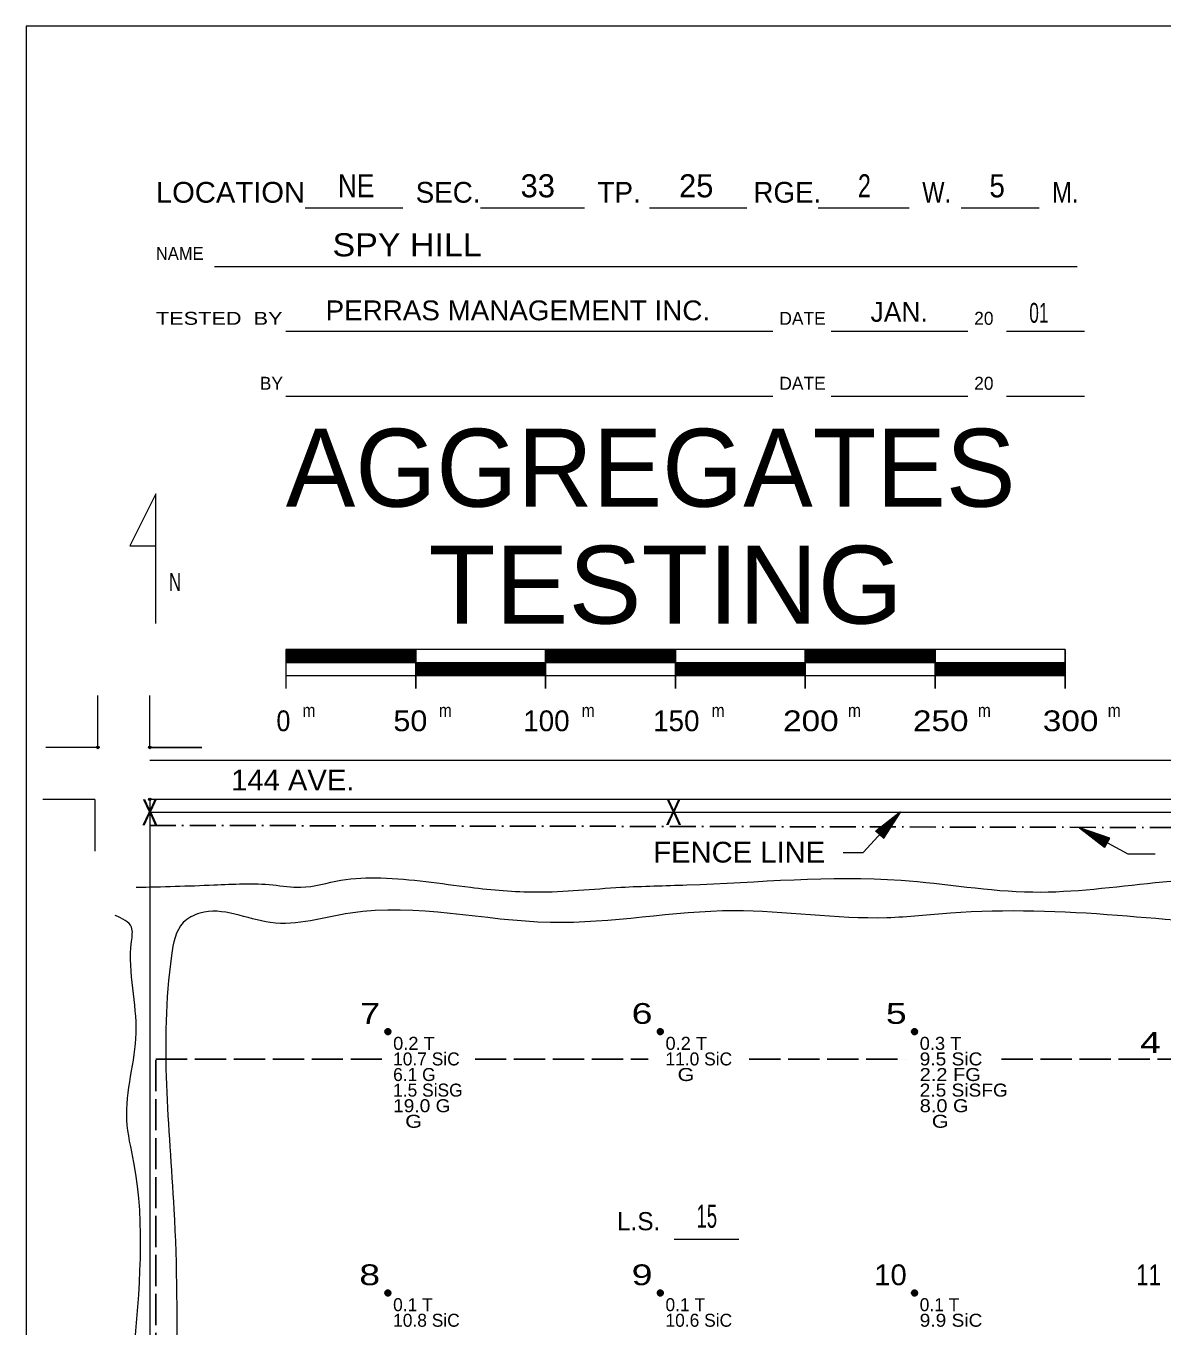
# Model space of a CAD drawing. Extents: x -496 to 480, y -450 to 700.
# Drawn here: x -450 to -12, y 199 to 700 of the extents above; entities that cross this region are included whole.
import ezdxf
from ezdxf.enums import TextEntityAlignment as Align

# ---------------------------------------------------------------- set-up
doc = ezdxf.new("R2010")
doc.units = 0
doc.header["$LTSCALE"] = 2
doc.header["$PDMODE"] = 32
doc.header["$PDSIZE"] = 1
doc.linetypes.add('DOT_DASHED', pattern=[7.7, 5, -1.2, 0.3, -1.2])
doc.linetypes.add('LONG_DASHED', pattern=[7.5, 6, -1.5])
for name, color, linetype, lineweight in [('1', 7, 'Continuous', 13), ('2', 7, 'Continuous', 35), ('3', 7, 'Continuous', 13), ('4', 7, 'Continuous', 25)]:
    doc.layers.add(name, color=color, linetype=linetype, lineweight=lineweight)

msp = doc.modelspace()

# ---------------------------------------------------------------- linework, layer by layer
at = {"layer": '1'}
for p, q in [((-342.517, 629.973), (-305.017, 629.973)), ((-275.017, 629.973), (-235.017, 629.973)), ((-210.017, 629.973), (-172.517, 629.973)), ((-145.017, 629.973), (-110.017, 629.973)), ((-90.017, 629.973), (-60.017, 629.973)), ((-377.517, 607.473), (-45.359, 607.473)), ((-350.017, 582.473), (-162.517, 582.473)), ((-140.017, 582.473), (-87.517, 582.473)), ((-72.517, 582.473), (-42.517, 582.473)), ((-350.017, 557.473), (-162.517, 557.473)), ((-140.017, 557.473), (-87.517, 557.473)), ((-72.517, 557.473), (-42.517, 557.473)), ((-350.017, 459.973), (-350.017, 444.973)), ((-50.017, 459.973), (-350.017, 459.973)), ((-350.017, 454.973), (-50.017, 454.973)), ((-422.391, 422.339), (-422.391, 442.339)), ((-402.391, 422.339), (-402.391, 442.339)), ((-422.391, 422.339), (-442.391, 422.339)), ((-423.537, 402.339), (-443.537, 402.339)), ((-423.537, 402.339), (-423.537, 382.339)), ((402.281, 402.339), (-402.391, 402.339)), ((-402.391, 402.339), (-402.391, -402.333)), ((-382.391, 402.339), (-402.391, 402.339)), ((-200.56, 233.082), (-175.56, 233.082))]:
    msp.add_line(p, q, dxfattribs=at)
at = {"layer": '1', "lineweight": 25}
for p, q in [((-350.017, 459.473), (-300.017, 459.473)), ((-350.017, 458.973), (-300.017, 458.973)), ((-350.017, 458.473), (-300.017, 458.473)), ((-350.017, 457.973), (-300.017, 457.973)), ((-350.017, 457.473), (-300.017, 457.473)), ((-350.017, 456.973), (-300.017, 456.973)), ((-350.017, 456.473), (-300.017, 456.473)), ((-350.017, 456.473), (-300.017, 456.473)), ((-350.017, 456.473), (-300.017, 456.473)), ((-350.017, 455.973), (-300.017, 455.973)), ((-350.017, 455.973), (-300.017, 455.973)), ((-300.017, 459.973), (-300.017, 444.973)), ((-250.017, 459.973), (-250.017, 444.973)), ((-250.017, 459.473), (-200.017, 459.473)), ((-250.017, 458.973), (-200.017, 458.973)), ((-250.017, 458.473), (-200.017, 458.473)), ((-250.017, 457.973), (-200.017, 457.973)), ((-250.017, 457.473), (-200.017, 457.473)), ((-250.017, 456.973), (-200.017, 456.973)), ((-250.017, 456.473), (-200.017, 456.473)), ((-250.017, 455.973), (-200.017, 455.973)), ((-200.017, 459.973), (-200.017, 444.973)), ((-150.017, 459.973), (-150.017, 444.973)), ((-150.017, 459.473), (-100.017, 459.473)), ((-150.017, 458.973), (-100.017, 458.973)), ((-150.017, 458.473), (-100.017, 458.473)), ((-150.017, 457.973), (-100.017, 457.973)), ((-150.017, 457.473), (-100.017, 457.473)), ((-150.017, 456.973), (-100.017, 456.973)), ((-150.017, 456.473), (-100.017, 456.473)), ((-150.017, 455.973), (-100.017, 455.973)), ((-100.017, 459.973), (-100.017, 444.973)), ((-50.017, 459.973), (-50.017, 444.973)), ((-350.017, 455.473), (-300.017, 455.473)), ((-300.017, 454.473), (-250.017, 454.473)), ((-300.017, 453.973), (-250.017, 453.973)), ((-300.017, 453.473), (-250.017, 453.473)), ((-300.017, 452.973), (-250.017, 452.973)), ((-300.017, 452.473), (-250.017, 452.473)), ((-300.017, 451.973), (-250.017, 451.973)), ((-300.017, 451.473), (-250.017, 451.473)), ((-300.017, 450.973), (-250.017, 450.973)), ((-250.017, 455.473), (-200.017, 455.473)), ((-200.017, 454.473), (-150.017, 454.473)), ((-200.017, 453.973), (-150.017, 453.973)), ((-200.017, 453.473), (-150.017, 453.473)), ((-200.017, 452.973), (-150.017, 452.973)), ((-200.017, 452.473), (-150.017, 452.473)), ((-200.017, 451.973), (-150.017, 451.973)), ((-200.017, 451.473), (-150.017, 451.473)), ((-200.017, 450.973), (-150.017, 450.973)), ((-150.017, 455.473), (-100.017, 455.473)), ((-100.017, 454.473), (-50.017, 454.473)), ((-100.017, 453.973), (-50.017, 453.973)), ((-100.017, 453.473), (-50.017, 453.473)), ((-100.017, 452.973), (-50.017, 452.973)), ((-100.017, 452.473), (-50.017, 452.473)), ((-100.017, 451.973), (-50.017, 451.973)), ((-100.017, 451.473), (-50.017, 451.473)), ((-100.017, 450.973), (-50.017, 450.973)), ((-300.017, 450.473), (-250.017, 450.473)), ((-200.017, 450.473), (-150.017, 450.473)), ((-100.017, 450.473), (-50.017, 450.473))]:
    msp.add_line(p, q, dxfattribs=at)
at = {"layer": '1'}
for points in [[(449.983, -450.027), (449.983, 399.973), (449.983, 699.973), (-450.017, 699.973), (-450.017, 49.973), (-450.017, -450.027)], [(-400.017, 469.973), (-400.017, 519.973), (-410.017, 499.973), (-400.017, 499.973)], [(-350.017, 449.973), (-50.017, 449.973), (-50.017, 459.973)], [(-402.391, 422.339), (-382.391, 422.339), (-402.391, 422.339)]]:
    msp.add_lwpolyline(points, dxfattribs=at)
for p in [(-422.391, 422.339), (-402.391, 422.339), (-402.391, 402.339)]:
    msp.add_point(p, dxfattribs=at)
at = {"layer": '2', "linetype": 'LONG_DASHED', "lineweight": 25}
for p, q in [((-400, -400), (-400, 302.339)), ((-400, 302.339), (-313.096, 302.339)), ((-277.172, 302.339), (-210.581, 302.339)), ((-171.59, 302.339), (-111.57, 302.339)), ((-74.459, 302.339), (302.281, 302.339))]:
    msp.add_line(p, q, dxfattribs=at)
at = {"layer": '2'}
for centre in [(-310.699, 312.939), (-205.849, 312.939), (-107.989, 312.939), (-310.699, 212.364), (-205.849, 212.364), (-107.989, 212.364)]:
    msp.add_circle(centre, 1, dxfattribs=at)
for points in [[(-310.71, 313.826), (-309.979, 313.422), (-309.828, 312.573), (-310.513, 312.045), (-311.322, 312.276), (-311.608, 313.034), (-311.361, 313.596), (-310.788, 313.764), (-310.114, 313.27), (-310.131, 312.528), (-310.648, 312.27), (-311.17, 312.439), (-311.395, 313.085), (-310.811, 313.551), (-310.373, 313.017), (-310.412, 312.534), (-311.041, 312.669), (-310.895, 313.304), (-310.603, 312.753)], [(-205.86, 313.826), (-205.129, 313.422), (-204.978, 312.573), (-205.663, 312.045), (-206.472, 312.276), (-206.758, 313.034), (-206.511, 313.596), (-205.938, 313.764), (-205.264, 313.27), (-205.281, 312.528), (-205.798, 312.27), (-206.32, 312.439), (-206.545, 313.085), (-205.961, 313.551), (-205.523, 313.017), (-205.562, 312.534), (-206.191, 312.669), (-206.045, 313.304), (-205.753, 312.753)], [(-108, 313.826), (-107.269, 313.422), (-107.118, 312.573), (-107.803, 312.045), (-108.612, 312.276), (-108.898, 313.034), (-108.651, 313.596), (-108.078, 313.764), (-107.404, 313.27), (-107.421, 312.528), (-107.938, 312.27), (-108.46, 312.439), (-108.685, 313.085), (-108.101, 313.551), (-107.663, 313.017), (-107.702, 312.534), (-108.331, 312.669), (-108.185, 313.304), (-107.893, 312.753)], [(-310.71, 213.251), (-309.979, 212.847), (-309.828, 211.998), (-310.513, 211.47), (-311.322, 211.701), (-311.608, 212.459), (-311.361, 213.021), (-310.788, 213.189), (-310.114, 212.695), (-310.131, 211.953), (-310.648, 211.695), (-311.17, 211.864), (-311.395, 212.51), (-310.811, 212.976), (-310.373, 212.442), (-310.412, 211.959), (-311.041, 212.094), (-310.895, 212.729), (-310.603, 212.178)], [(-205.86, 213.251), (-205.129, 212.847), (-204.978, 211.998), (-205.663, 211.47), (-206.472, 211.701), (-206.758, 212.459), (-206.511, 213.021), (-205.938, 213.189), (-205.264, 212.695), (-205.281, 211.953), (-205.798, 211.695), (-206.32, 211.864), (-206.545, 212.51), (-205.961, 212.976), (-205.523, 212.442), (-205.562, 211.959), (-206.191, 212.094), (-206.045, 212.729), (-205.753, 212.178)], [(-108, 213.251), (-107.269, 212.847), (-107.118, 211.998), (-107.803, 211.47), (-108.612, 211.701), (-108.898, 212.459), (-108.651, 213.021), (-108.078, 213.189), (-107.404, 212.695), (-107.421, 211.953), (-107.938, 211.695), (-108.46, 211.864), (-108.685, 212.51), (-108.101, 212.976), (-107.663, 212.442), (-107.702, 211.959), (-108.331, 212.094), (-108.185, 212.729), (-107.893, 212.178)]]:
    msp.add_spline(points, degree=3, dxfattribs=at)
at = {"layer": '3'}
for p, q in [((402.281, 417.339), (-402.391, 417.339)), ((402.281, 397.339), (-402.391, 397.339))]:
    msp.add_line(p, q, dxfattribs=at)
at = {"layer": '3', "linetype": 'DOT_DASHED', "lineweight": 25}
msp.add_line((-402.402, 392.339), (376.548, 390.701), dxfattribs=at)
at = {"layer": '3'}
msp.add_spline([(-407.583, 368.504), (-377.691, 369.409), (-355.045, 369.409), (-344.175, 368.504), (-328.776, 371.218), (-313.377, 372.123), (-278.956, 368.504), (-253.593, 366.695), (-220.983, 368.504), (-195.62, 369.409), (-113.189, 371.218), (-62.463, 366.695), (-15.36, 370.314), (129.573, 369.409), (163.088, 366.695), (215.626, 369.409), (283.563, 369.409), (313.456, 370.314), (344.254, 369.409), (357.841, 369.409), (358.747, 364.885), (359.653, 358.552), (346.971, 354.028), (317.985, 355.837), (282.658, 358.552), (167.617, 358.552), (86.999, 357.647), (29.026, 354.028), (-29.853, 357.647), (-94.167, 358.552), (-118.624, 356.742), (-177.503, 359.456), (-248.158, 354.932), (-325.153, 358.552), (-355.951, 354.932), (-383.126, 358.552), (-389.467, 354.932), (-393.996, 342.265), (-393.09, 244.549), (-392.184, 178.5), (-393.996, 113.356), (-393.996, 88.927), (-393.09, 59.974), (-392.184, 33.736), (-397.619, 15.64), (-404.866, 15.64), (-411.207, 31.021), (-407.583, 90.737), (-410.301, 145.024), (-408.489, 188.453), (-408.489, 262.645), (-411.207, 278.931), (-407.583, 312.408), (-409.395, 347.694), (-409.395, 353.123), (-415.736, 357.647)], degree=3, dxfattribs=at)
at = {"layer": '4', "lineweight": 13}
for points in [[(-135.445, 381.875), (-127.763, 381.875), (-113.321, 397.528)], [(-15.299, 381.261), (-25.747, 381.261), (-44.491, 391.389)]]:
    msp.add_lwpolyline(points, dxfattribs=at)
at = {"layer": '4'}
for points in [[(-113.321, 397.528), (-122.928, 390.064), (-119.988, 387.352)], [(-44.491, 391.389), (-34.884, 383.925), (-32.983, 387.444)]]:
    msp.add_lwpolyline(points, close=True, dxfattribs=at)
for points in [[(-122.775, 390.056), (-113.71, 397.107), (-119.998, 387.583), (-122.617, 389.971), (-114.21, 396.565), (-119.992, 387.842), (-122.39, 389.994), (-114.738, 395.993), (-120.021, 388.133), (-122.144, 389.944), (-115.353, 395.357), (-120.002, 388.44), (-121.836, 389.956), (-116.089, 394.593), (-120.06, 388.759), (-121.499, 389.939), (-116.881, 393.767), (-120.109, 389.185), (-121.15, 389.969), (-117.78, 392.888), (-120.066, 389.614), (-120.74, 390.031), (-118.776, 391.777), (-120.071, 390.148)], [(-34.914, 384.076), (-43.986, 391.116), (-33.204, 387.377), (-34.87, 384.25), (-43.338, 390.766), (-33.456, 387.319), (-34.949, 384.463), (-42.653, 390.396), (-33.731, 387.22), (-34.961, 384.715), (-41.885, 389.957), (-34.034, 387.162), (-35.049, 385.01), (-40.963, 389.432), (-34.328, 387.026), (-35.115, 385.34), (-39.966, 388.87), (-34.729, 386.874), (-35.231, 385.672), (-38.892, 388.216), (-35.155, 386.81), (-35.393, 386.054), (-37.57, 387.525), (-35.672, 386.673)]]:
    msp.add_lwpolyline(points, dxfattribs=at)

# ---------------------------------------------------------------- texts
at = {"layer": '1'}
for s, height, width, p in [('NE', 8.89, 0.85, (-322.943, 634.038)), ('2', 8.89, 0.75, (-127.28, 634.037)), ('5', 8.89, 0.9, (-76.181, 634.038)), ('SPY HILL', 8.89, 1.1, (-303.323, 611.329)), ('PERRAS MANAGEMENT INC.', 7.62, 1.05, (-260.682, 586.728)), ('01', 7.62, 0.65, (-60.119, 585.781)), ('15', 8.89, 0.6, (-187.963, 237.471))]:
    msp.add_text(s, height=height, dxfattribs=dict(at, width=width)).set_placement(p, align=Align.CENTER)
for s, height, p in [('33', 8.89, (-253.021, 634.038)), ('25', 8.89, (-192.027, 634.038)), ('JAN.', 7.62, (-113.875, 586.148)), ('L.S.', 7, (-214.167, 236.497))]:
    msp.add_text(s, height=height, dxfattribs=at).set_placement(p, align=Align.CENTER)
for s, height, width, p in [('LOCATION', 8, 1.05, (-400.017, 631.973)), ('W.', 8, 0.85, (-105.017, 631.973)), ('M.', 8, 0.85, (-55.017, 631.973)), ('NAME', 5, 0.95, (-400.017, 609.973)), ('TESTED  BY', 5, 1.25, (-400.017, 584.973)), ('TESTING', 30, 1.05, (-295.017, 469.973)), ('N', 7, 0.7, (-395.017, 482.473)), ('0', 8, 0.9, (-353.607, 428.573)), ('m', 5, 0.9, (-343.607, 434.073)), ('50', 8, 1.1, (-308.607, 428.573)), ('m', 5, 0.9, (-291.107, 434.073)), ('m', 5, 0.9, (-236.107, 434.073)), ('m', 5, 0.9, (-186.107, 434.073)), ('200', 8, 1.2, (-158.607, 428.573)), ('m', 5, 0.9, (-133.607, 434.073)), ('250', 8, 1.2, (-108.607, 428.573)), ('m', 5, 0.9, (-83.607, 434.073)), ('300', 8, 1.2, (-58.607, 428.573)), ('m', 5, 0.9, (-33.607, 434.073))]:
    msp.add_text(s, height=height, dxfattribs=dict(at, width=width)).set_placement(p)
for s, height, p in [('SEC.', 8, (-300.017, 631.973)), ('TP.', 8, (-230.017, 631.973)), ('RGE.', 8, (-170.017, 631.973)), ('DATE', 5, (-160.017, 584.973)), ('20', 5, (-85.017, 584.973)), ('BY', 5, (-360.017, 559.973)), ('DATE', 5, (-160.017, 559.973)), ('20', 5, (-85.017, 559.973)), ('AGGREGATES', 30, (-350.017, 514.973)), ('100', 8, (-258.607, 428.573)), ('150', 8, (-208.607, 428.573))]:
    msp.add_text(s, height=height, dxfattribs=at).set_placement(p)
at = {"layer": '2'}
for s, width, p in [('  7', 1.3, (-313.699, 315.939)), ('  6', 1.35, (-208.849, 315.939)), ('  5', 1.35, (-110.989, 315.939)), ('  4', 1.35, (-13.129, 304.764)), ('  8', 1.35, (-313.699, 215.364)), ('  9', 1.35, (-208.849, 215.364)), (' 10', 1.05, (-110.989, 215.364)), (' 11', 0.8, (-13.129, 215.364))]:
    msp.add_text(s, height=8, dxfattribs=dict(at, width=width)).set_placement(p, align=Align.RIGHT)
for s, width, p in [('0.2 T      ', 1.05, (-308.699, 305.939)), ('0.2 T      ', 1.05, (-203.849, 305.939)), ('0.3 T      ', 1.05, (-105.989, 305.939)), ('9.5 SiC    ', 1.1, (-105.989, 299.939)), ('  G        ', 1.25, (-203.849, 293.939)), ('2.2 FG     ', 1.15, (-105.989, 293.939)), ('2.5 SiSFG  ', 1.1, (-105.989, 287.939)), ('19.0 G     ', 1.1, (-308.699, 281.939)), ('8.0 G      ', 1.15, (-105.989, 281.939)), ('  G        ', 1.25, (-308.699, 275.939)), ('  G        ', 1.25, (-105.989, 275.939)), ('9.9 SiC    ', 1.1, (-105.989, 199.364))]:
    msp.add_text(s, height=5, dxfattribs=dict(at, width=width)).set_placement(p)
for s, p in [('10.7 SiC   ', (-308.699, 299.939)), ('11.0 SiC   ', (-203.849, 299.939)), ('6.1 G      ', (-308.699, 293.939)), ('1.5 SiSG   ', (-308.699, 287.939)), ('0.1 T      ', (-308.699, 205.364)), ('0.1 T      ', (-203.849, 205.364)), ('0.1 T      ', (-105.989, 205.364)), ('10.8 SiC   ', (-308.699, 199.364)), ('10.6 SiC   ', (-203.849, 199.364))]:
    msp.add_text(s, height=5, dxfattribs=at).set_placement(p)
at = {"layer": '3', "width": 0.7}
for p in [(-402.344, 392.358), (-200.737, 392.465)]:
    msp.add_text('X', height=10, dxfattribs=at).set_placement(p, align=Align.CENTER)
at = {"layer": '4', "width": 1.05}
for s, p in [('144 AVE.', (-347.316, 405.765)), ('FENCE LINE', (-175.481, 378.012))]:
    msp.add_text(s, height=8, dxfattribs=at).set_placement(p, align=Align.CENTER)

doc.saveas('drawing.dxf')
